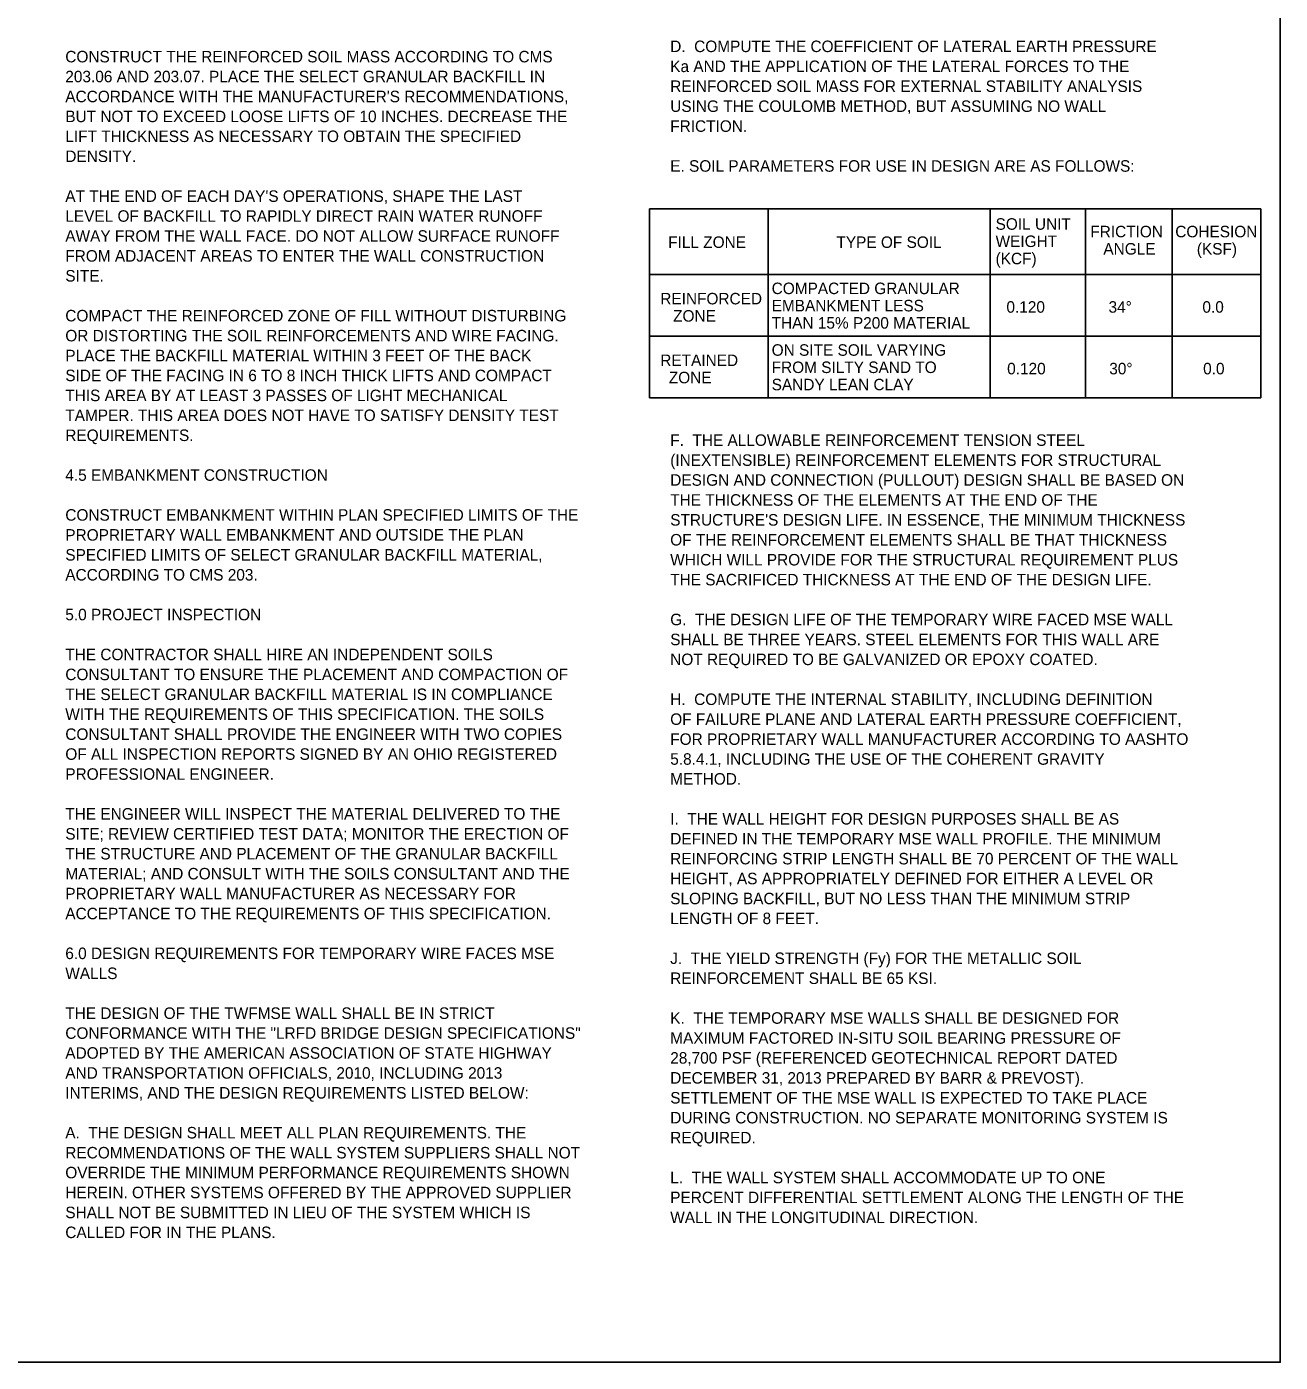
# Model space of a CAD drawing. Extents: x 1530552 to 1530730, y 675304 to 675366.
# Drawn here: x 1530570.44 to 1530585.69, y 675304.35 to 675320.6 of the extents above; entities that cross this region are included whole.
import ezdxf

# ---------------------------------------------------------------- set-up
doc = ezdxf.new("R2010")
doc.units = 0
doc.layers.add('BR_P_Gen_Text', color=7, linetype='Continuous')

msp = doc.modelspace()

# ---------------------------------------------------------------- linework, layer by layer
at = {"layer": 'BR_P_Gen_Text'}
for p, q in [((1530578.016, 675318.384), (1530585.453, 675318.384)), ((1530578.016, 675316.084), (1530578.016, 675318.384)), ((1530579.457, 675316.077), (1530579.457, 675318.377)), ((1530582.16, 675316.084), (1530582.16, 675318.384)), ((1530583.319, 675316.084), (1530583.319, 675318.384)), ((1530584.372, 675316.084), (1530584.372, 675318.384)), ((1530585.453, 675318.384), (1530585.453, 675316.084)), ((1530585.453, 675317.584), (1530578.016, 675317.584)), ((1530585.453, 675316.834), (1530578.016, 675316.834)), ((1530585.453, 675316.084), (1530578.016, 675316.084))]:
    msp.add_line(p, q, dxfattribs=at)
msp.add_lwpolyline([(1530555.188, 675325.353), (1530585.688, 675325.353), (1530585.688, 675304.353), (1530555.188, 675304.353)], close=True, dxfattribs=at)

# ---------------------------------------------------------------- texts
for s, p in [('D.  COMPUTE THE COEFFICIENT OF LATERAL EARTH PRESSURE ', (1530578.267, 675320.291)), ('CONSTRUCT THE REINFORCED SOIL MASS ACCORDING TO CMS ', (1530570.908, 675320.166)), ('203.06 AND 203.07. PLACE THE SELECT GRANULAR BACKFILL IN ', (1530570.908, 675319.924)), ('Ka AND THE APPLICATION OF THE LATERAL FORCES TO THE ', (1530578.267, 675320.048)), ('REINFORCED SOIL MASS FOR EXTERNAL STABILITY ANALYSIS ', (1530578.267, 675319.806)), ("ACCORDANCE WITH THE MANUFACTURER'S RECOMMENDATIONS, ", (1530570.908, 675319.681)), ('BUT NOT TO EXCEED LOOSE LIFTS OF 10 INCHES. DECREASE THE ', (1530570.908, 675319.439)), ('USING THE COULOMB METHOD, BUT ASSUMING NO WALL ', (1530578.267, 675319.563)), ('FRICTION.', (1530578.267, 675319.321)), ('LIFT THICKNESS AS NECESSARY TO OBTAIN THE SPECIFIED ', (1530570.908, 675319.197)), ('DENSITY.', (1530570.908, 675318.954)), ('E. SOIL PARAMETERS FOR USE IN DESIGN ARE AS FOLLOWS:', (1530578.267, 675318.836)), ("AT THE END OF EACH DAY'S OPERATIONS, SHAPE THE LAST ", (1530570.908, 675318.469)), ('LEVEL OF BACKFILL TO RAPIDLY DIRECT RAIN WATER RUNOFF ', (1530570.908, 675318.227)), ('SOIL UNIT', (1530582.225, 675318.13)), ('AWAY FROM THE WALL FACE. DO NOT ALLOW SURFACE RUNOFF ', (1530570.908, 675317.984)), ('FRICTION', (1530583.377, 675318.038)), ('COHESION', (1530584.411, 675318.038)), ('FILL ZONE', (1530578.242, 675317.909)), ('TYPE OF SOIL', (1530580.289, 675317.909)), ('WEIGHT', (1530582.225, 675317.92)), ('ANGLE', (1530583.536, 675317.828)), ('(KSF)', (1530584.673, 675317.828)), ('FROM ADJACENT AREAS TO ENTER THE WALL CONSTRUCTION ', (1530570.908, 675317.742)), ('(KCF)', (1530582.225, 675317.71)), ('SITE.', (1530570.908, 675317.5)), ('COMPACTED GRANULAR', (1530579.501, 675317.347)), ('REINFORCED', (1530578.146, 675317.222)), ('COMPACT THE REINFORCED ZONE OF FILL WITHOUT DISTURBING ', (1530570.908, 675317.015)), ('   ZONE', (1530578.146, 675317.012)), ('EMBANKMENT LESS', (1530579.501, 675317.137)), ('0.120', (1530582.357, 675317.121)), ('34%%D', (1530583.599, 675317.121)), ('0.0', (1530584.741, 675317.121)), ('THAN 15% P200 MATERIAL', (1530579.501, 675316.927)), ('OR DISTORTING THE SOIL REINFORCEMENTS AND WIRE FACING. ', (1530570.908, 675316.772)), ('PLACE THE BACKFILL MATERIAL WITHIN 3 FEET OF THE BACK ', (1530570.908, 675316.53)), ('ON SITE SOIL VARYING', (1530579.501, 675316.597)), ('RETAINED', (1530578.146, 675316.472)), ('FROM SILTY SAND TO', (1530579.501, 675316.387)), ('0.120', (1530582.366, 675316.371)), ('30%%D', (1530583.608, 675316.371)), ('0.0', (1530584.75, 675316.371)), ('SIDE OF THE FACING IN 6 TO 8 INCH THICK LIFTS AND COMPACT ', (1530570.908, 675316.288)), ('  ZONE', (1530578.146, 675316.262)), ('THIS AREA BY AT LEAST 3 PASSES OF LIGHT MECHANICAL ', (1530570.908, 675316.045)), ('SANDY LEAN CLAY', (1530579.501, 675316.177)), ('TAMPER. THIS AREA DOES NOT HAVE TO SATISFY DENSITY TEST ', (1530570.908, 675315.803)), ('REQUIREMENTS.', (1530570.908, 675315.56)), ('F.  THE ALLOWABLE REINFORCEMENT TENSION STEEL ', (1530578.267, 675315.501)), ('(INEXTENSIBLE) REINFORCEMENT ELEMENTS FOR STRUCTURAL ', (1530578.267, 675315.258)), ('4.5 EMBANKMENT CONSTRUCTION', (1530570.908, 675315.076)), ('DESIGN AND CONNECTION (PULLOUT) DESIGN SHALL BE BASED ON ', (1530578.267, 675315.016)), ('THE THICKNESS OF THE ELEMENTS AT THE END OF THE ', (1530578.267, 675314.773)), ('CONSTRUCT EMBANKMENT WITHIN PLAN SPECIFIED LIMITS OF THE ', (1530570.908, 675314.591)), ("STRUCTURE'S DESIGN LIFE. IN ESSENCE, THE MINIMUM THICKNESS ", (1530578.267, 675314.531)), ('PROPRIETARY WALL EMBANKMENT AND OUTSIDE THE PLAN ', (1530570.908, 675314.348)), ('OF THE REINFORCEMENT ELEMENTS SHALL BE THAT THICKNESS ', (1530578.267, 675314.289)), ('SPECIFIED LIMITS OF SELECT GRANULAR BACKFILL MATERIAL, ', (1530570.908, 675314.106)), ('WHICH WILL PROVIDE FOR THE STRUCTURAL REQUIREMENT PLUS ', (1530578.267, 675314.046)), ('ACCORDING TO CMS 203.', (1530570.908, 675313.863)), ('THE SACRIFICED THICKNESS AT THE END OF THE DESIGN LIFE.', (1530578.267, 675313.804)), ('5.0 PROJECT INSPECTION', (1530570.908, 675313.379)), ('G.  THE DESIGN LIFE OF THE TEMPORARY WIRE FACED MSE WALL ', (1530578.267, 675313.319)), ('SHALL BE THREE YEARS. STEEL ELEMENTS FOR THIS WALL ARE ', (1530578.267, 675313.076)), ('THE CONTRACTOR SHALL HIRE AN INDEPENDENT SOILS ', (1530570.908, 675312.894)), ('NOT REQUIRED TO BE GALVANIZED OR EPOXY COATED.', (1530578.267, 675312.834)), ('CONSULTANT TO ENSURE THE PLACEMENT AND COMPACTION OF ', (1530570.908, 675312.651)), ('THE SELECT GRANULAR BACKFILL MATERIAL IS IN COMPLIANCE ', (1530570.908, 675312.409)), ('H.  COMPUTE THE INTERNAL STABILITY, INCLUDING DEFINITION ', (1530578.267, 675312.349)), ('WITH THE REQUIREMENTS OF THIS SPECIFICATION. THE SOILS ', (1530570.908, 675312.167)), ('OF FAILURE PLANE AND LATERAL EARTH PRESSURE COEFFICIENT, ', (1530578.267, 675312.107)), ('CONSULTANT SHALL PROVIDE THE ENGINEER WITH TWO COPIES ', (1530570.908, 675311.924)), ('FOR PROPRIETARY WALL MANUFACTURER ACCORDING TO AASHTO ', (1530578.267, 675311.864)), ('OF ALL INSPECTION REPORTS SIGNED BY AN OHIO REGISTERED ', (1530570.908, 675311.682)), ('5.8.4.1, INCLUDING THE USE OF THE COHERENT GRAVITY ', (1530578.267, 675311.622)), ('PROFESSIONAL ENGINEER.', (1530570.908, 675311.439)), ('METHOD.', (1530578.267, 675311.38)), ('THE ENGINEER WILL INSPECT THE MATERIAL DELIVERED TO THE ', (1530570.908, 675310.955)), ('I.  THE WALL HEIGHT FOR DESIGN PURPOSES SHALL BE AS ', (1530578.267, 675310.895)), ('SITE; REVIEW CERTIFIED TEST DATA; MONITOR THE ERECTION OF ', (1530570.908, 675310.712)), ('DEFINED IN THE TEMPORARY MSE WALL PROFILE. THE MINIMUM ', (1530578.267, 675310.652)), ('THE STRUCTURE AND PLACEMENT OF THE GRANULAR BACKFILL ', (1530570.908, 675310.47)), ('REINFORCING STRIP LENGTH SHALL BE 70 PERCENT OF THE WALL ', (1530578.267, 675310.41)), ('MATERIAL; AND CONSULT WITH THE SOILS CONSULTANT AND THE ', (1530570.908, 675310.227)), ('HEIGHT, AS APPROPRIATELY DEFINED FOR EITHER A LEVEL OR ', (1530578.267, 675310.168)), ('PROPRIETARY WALL MANUFACTURER AS NECESSARY FOR ', (1530570.908, 675309.985)), ('SLOPING BACKFILL, BUT NO LESS THAN THE MINIMUM STRIP ', (1530578.267, 675309.925)), ('ACCEPTANCE TO THE REQUIREMENTS OF THIS SPECIFICATION.', (1530570.908, 675309.742)), ('LENGTH OF 8 FEET.', (1530578.267, 675309.683)), ('6.0 DESIGN REQUIREMENTS FOR TEMPORARY WIRE FACES MSE ', (1530570.908, 675309.258)), ('J.  THE YIELD STRENGTH (Fy) FOR THE METALLIC SOIL ', (1530578.267, 675309.198)), ('WALLS', (1530570.908, 675309.015)), ('REINFORCEMENT SHALL BE 65 KSI.', (1530578.267, 675308.955)), ('THE DESIGN OF THE TWFMSE WALL SHALL BE IN STRICT ', (1530570.908, 675308.53)), ('K.  THE TEMPORARY MSE WALLS SHALL BE DESIGNED FOR ', (1530578.267, 675308.471)), ('CONFORMANCE WITH THE "LRFD BRIDGE DESIGN SPECIFICATIONS" ', (1530570.908, 675308.288)), ('MAXIMUM FACTORED IN-SITU SOIL BEARING PRESSURE OF ', (1530578.267, 675308.228)), ('ADOPTED BY THE AMERICAN ASSOCIATION OF STATE HIGHWAY ', (1530570.908, 675308.046)), ('28,700 PSF (REFERENCED GEOTECHNICAL REPORT DATED ', (1530578.267, 675307.986)), ('AND TRANSPORTATION OFFICIALS, 2010, INCLUDING 2013 ', (1530570.908, 675307.803)), ('DECEMBER 31, 2013 PREPARED BY BARR & PREVOST). ', (1530578.267, 675307.743)), ('INTERIMS, AND THE DESIGN REQUIREMENTS LISTED BELOW:', (1530570.908, 675307.561)), ('SETTLEMENT OF THE MSE WALL IS EXPECTED TO TAKE PLACE ', (1530578.267, 675307.501)), ('DURING CONSTRUCTION. NO SEPARATE MONITORING SYSTEM IS ', (1530578.267, 675307.259)), ('A.  THE DESIGN SHALL MEET ALL PLAN REQUIREMENTS. THE ', (1530570.908, 675307.076)), ('REQUIRED.', (1530578.267, 675307.016)), ('RECOMMENDATIONS OF THE WALL SYSTEM SUPPLIERS SHALL NOT ', (1530570.908, 675306.833)), ('OVERRIDE THE MINIMUM PERFORMANCE REQUIREMENTS SHOWN ', (1530570.908, 675306.591)), ('L.  THE WALL SYSTEM SHALL ACCOMMODATE UP TO ONE ', (1530578.267, 675306.531)), ('HEREIN. OTHER SYSTEMS OFFERED BY THE APPROVED SUPPLIER ', (1530570.908, 675306.349)), ('PERCENT DIFFERENTIAL SETTLEMENT ALONG THE LENGTH OF THE ', (1530578.267, 675306.289)), ('SHALL NOT BE SUBMITTED IN LIEU OF THE SYSTEM WHICH IS ', (1530570.908, 675306.106)), ('WALL IN THE LONGITUDINAL DIRECTION.', (1530578.267, 675306.046)), ('CALLED FOR IN THE PLANS.', (1530570.908, 675305.864))]:
    msp.add_text(s, height=0.14, dxfattribs=at).set_placement(p)

doc.saveas('drawing.dxf')
